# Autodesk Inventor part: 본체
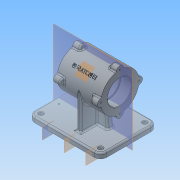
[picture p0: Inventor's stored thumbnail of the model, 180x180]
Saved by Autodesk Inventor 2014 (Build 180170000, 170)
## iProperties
Created: 2015-12
Part Number: 본체
Material: 일반
Document SubType Name: Modeling
Designer: nert
Density: 1 g/cm^3
Appearance: 기본값
Mass: 429.95 g
Surface Area: 814.906 cm^2
Volume: 429.95 cm^3
Author: nert
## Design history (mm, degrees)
sketch "스케치1"
  geometry: L1 (-70, 55)-(70, 55); L2 (70, 55)-(70, -55); L3 (70, -55)-(-70, -55); L4 (-70, -55)-(-70, 55); 3 further points
  constraints: 8 end point, 2 midpoint, 2 parallel, 1 horizontal, 1 horizontal alignment, 1 perpendicular, 1 vertical alignment
  dimensions: "d0" = 140 distance between parallel lines of L2 L4; "d1" = 110 distance between parallel lines of L3 L1
extrude "돌출1" new body sketch "스케치1" distance "d2" = 10; taper "d3" = 0 deg
node "작업 평면1"
node "작업 평면6"
  node "작업 평면5"
sketch "스케치5"
  geometry: C1 r 37 at (80, 55); 1 further point
  constraints: 1 centre point, 1 horizontal alignment
  dimensions: "d28" = 74 diameter of C1; "d29" = 80 distance of point (0, 55) C1.centre
extrude "돌출4" join sketch "스케치5" stored distance "d30" = 85; taper "d31" = 0 deg
sketch "스케치6"
  geometry: L1 (-52.5, 117)-(-52.5, 43) reference; L2 (-52.5, 80)-(32.5, 80); L3 (32.5, 43)-(32.5, 117) reference; L4 (-52.5, 103.5)-(-30.5, 103.5); L5 (-30.5, 103.5)-(-30.5, 80); L6 (-30.5, 101)-(10.5, 101); L7 (10.5, 101)-(10.5, 80); L8 (10.5, 101)-(10.5, 103.5); L9 (10.5, 103.5)-(32.5, 103.5); 1 further point
  constraints: 14 end point, 5 perpendicular, 5 point on line, 2 collinear, 2 midpoint, 1 horizontal
  dimensions: "d32" = 47 diameter of L4 L2; "d33" = 42 diameter of L6 L2; "d34" = 22 distance between parallel lines of L1 L5; "d35" = 22 distance between parallel lines of L3 L7
revolve "회전1" sketch "스케치6" stored, may be unused: angle "d36" = 90 deg
node "작업 평면7"
sketch "스케치7"
  geometry: L1 (-70, 55)-(70, 55) reference; L2 (70, 55)-(70, -55) reference; L3 (70, -55)-(-70, -55) reference; L4 (-70, -55)-(-70, 55) reference; L5 (14, 37)-(6, 37); L6 (6, 37)-(6, -37); L7 (6, -37)-(14, -37); L8 (14, -37)-(14, 37); 3 further points
  constraints: 8 end point, 3 midpoint, 2 parallel, 1 horizontal, 1 horizontal alignment, 1 perpendicular
  dimensions: "d38" = 8 distance between parallel lines of L6 L8; "d39" = 74 distance between parallel lines of L5 L7; "d40" = 80 distance from line of L4 point (10, 37); "d41" = 55 distance from line of point (6, 0) L3
extrude "돌출5" join sketch "스케치7" stored distance "d42" = 85; taper "d43" = 0 deg
node "작업 평면8"
node "작업 평면9"
node "작업 평면11"
node "작업 평면12"
sketch "스케치11"
  geometry: L1 (35, 6)-(-15, 6); L2 (-15, 6)-(-15, -6); L3 (-15, -6)-(35, -6); L4 (35, -6)-(35, 6); L5 (70, 55)-(70, -55) reference; 3 further points
  constraints: 8 end point, 2 midpoint, 2 parallel, 1 horizontal, 1 horizontal alignment, 1 perpendicular
  dimensions: "d58" = 35 distance between parallel lines of L5 L4; "d59" = 50 distance between parallel lines of L4 L2; "d60" = 12 distance between parallel lines of L1 L3
extrude "돌출7" join sketch "스케치11" stored distance "d61" = 12; taper "d62" = 0 deg
node "작업 평면13"
sketch "스케치12"
  geometry: L1 (-29, 0)-(-29, 33.49) reference; L2 (-8, 33.49)-(-29, 33.49) reference; L3 (21, 33.49)-(0, 33.49) reference; L4 (21, 0)-(21, 33.49) reference; L5 (-29, 0)-(-24.888, 33.49); L6 (-29, 0)-(-8, 0) reference; L7 (-8, 0)-(-8, 33.49) reference; L8 (21, 0)-(16.888, 33.49); L9 (0, 0)-(21, 0) reference; 1 further point
  constraints: 4 end point, 2 point on line
  dimensions: "d63" = 97 deg angle of L6 L5; "d64" = 97 deg angle of L9 L8
extrude "돌출8" cut sketch "스케치12" stored distance "d65" = 12; taper "d66" = 0 deg
node "작업 평면14"
sketch "스케치13"
  geometry: C1 r 23.5 at (0, 0) reference; C2 r 37 at (0, 0) reference; C3 r 23.5 at (0, 0); C4 r 37 at (0, 0); 1 further point
  constraints: 2 centre point, 2 coincident, 2 concentric
extrude "돌출9" join sketch "스케치13" stored distance "d67" = 50; taper "d68" = 0 deg
node "작업 평면15"
sketch "스케치14"
  geometry: A1 r 7 centre (-37, 0) between (-36.338, 6.969) and (-36.338, -6.969); A2 r 7 centre (0, -37) between (-6.969, -36.338) and (6.969, -36.338); A3 r 7 centre (37, 0) between (36.338, -6.969) and (36.338, 6.969); A4 r 7 centre (0, 37) between (6.969, 36.338) and (-6.969, 36.338); 2 further points
  constraints: 8 point on circle, 4 centre point, 3 equal radius, 2 horizontal alignment, 2 vertical alignment, 13 other
  dimensions: "d70" = 14 diameter of A1
extrude "돌출10" join sketch "스케치14" distance "d71" = 15; taper "d72" = 0 deg
node "작업 평면16"
node "작업 평면17"
node "작업 평면18"
sketch "스케치16"
  geometry: L1 (-52.5, 116.338)-(-52.5, 116.338) reference; L2 (-37.5, 116.338)-(-52.5, 116.338) reference; L3 (-37.5, 116.338)-(-37.5, 116.338) reference; L4 (-52.5, 116.338)-(-37.5, 116.338) reference; L5 (-52.5, 124)-(-37.5, 124) reference; L6 (-37.5, 117)-(17.5, 117) reference; L7 (-40.289, 124)-(-37.5, 124); L8 (-37.5, 116.338)-(-40.289, 124); L9 (-40.289, 124)-(-40.289, 124); L10 (-37.5, 116.338)-(-37.5, 124); 1 further point
  constraints: 8 end point, 2 point on line, 1 perpendicular
  dimensions: "d85" = 110 deg angle of L2 L8
extrude "돌출11" cut sketch "스케치16" stored distance "d86" = 15; taper "d87" = 0 deg
node "작업 평면19"
node "작업 평면20"
sketch "스케치17"
  geometry: L1 (-70, -55)-(70, -55) reference; L2 (-70, 55)-(-70, -55) reference; C1 r 4 at (-58, -43); 1 further point
  constraints: 1 centre point
  dimensions: "d92" = 12 distance from line of L1 C1.centre; "d93" = 12 distance from line of C1.centre L2; "d94" = 8 diameter of C1
extrude "돌출12" cut sketch "스케치17" distance "d95" = 15; taper "d96" = 0 deg
node "작업 평면21"
node "작업 평면22"
fillet "모깎기2" dims "d98" = 3
node "작업 평면23"
sketch "스케치18"
  geometry: C1 r 37 at (80, 55); C2 r 21 at (80, 55) reference; C3 r 23.5 at (80, 55) reference; C4 r 23.5 at (80, 55); A1 r 37 centre (80, 55) between (86.969, 18.662) and (116.338, 48.031) reference; 1 further point
  constraints: 2 centre point, 2 coincident, 1 concentric
  dimensions: "d99" = 74 diameter of C1
extrude "돌출13" join sketch "스케치18" stored distance "d100" = 85; taper "d101" = 0 deg
fillet "모깎기3" dims "d102" = 3
node "작업 평면29"
sketch "스케치19"
  geometry: A1 r 7 centre (117, 55) between (118.239, 48.111) and (118.239, 61.889) reference; 2 further points
  constraints: 1 coincident
hole "구멍2" sketch "스케치19" at (117, 55) diameter "d104" = 3.242; stored, may be unused: countersink angle "d108" = 90 deg, drill point angle "d110" = 118 deg; dims "d105" = 9, "d106" = 4, "d107" = 2, "d109" = 11
node "작업 평면31"
sketch "스케치20"
  geometry: C1 r 23.5 at (-80, 55) reference; A1 r 7 centre (-43, 55) between (-41.761, 48.111) and (-41.761, 61.889) reference; A2 r 3 centre (-41.23, 64.842) between (-44.138, 64.104) and (-41.761, 61.889) reference; A3 r 37 centre (-80, 55) between (-44.138, 64.104) and (-70.896, 90.862) reference; A4 r 3 centre (-70.158, 93.77) between (-73.111, 93.239) and (-70.896, 90.862) reference; A5 r 7 centre (-80, 92) between (-73.111, 93.239) and (-86.889, 93.239) reference; A6 r 3 centre (-89.842, 93.77) between (-89.104, 90.862) and (-86.889, 93.239) reference; A7 r 37 centre (-80, 55) between (-89.104, 90.862) and (-115.862, 64.104) reference; A8 r 3 centre (-118.77, 64.842) between (-118.239, 61.889) and (-115.862, 64.104) reference; A9 r 7 centre (-117, 55) between (-118.239, 61.889) and (-118.239, 48.111) reference; A10 r 3 centre (-118.77, 45.158) between (-115.862, 45.896) and (-118.239, 48.111) reference; A11 r 37 centre (-80, 55) between (-115.862, 45.896) and (-89.104, 19.137) reference; A12 r 3 centre (-89.842, 16.23) between (-86.889, 16.761) and (-89.104, 19.137) reference; A13 r 7 centre (-80, 18) between (-86.889, 16.761) and (-73.111, 16.761) reference; A14 r 3 centre (-70.158, 16.23) between (-70.896, 19.137) and (-73.111, 16.761) reference; A15 r 37 centre (-80, 55) between (-70.896, 19.137) and (-44.138, 45.896) reference; A16 r 3 centre (-41.23, 45.158) between (-41.761, 48.111) and (-44.138, 45.896) reference; 4 further points
  constraints: 3 coincident
hole "구멍3" sketch "스케치20" at (-80, 92), (-43, 55), (-80, 18) diameter "d115" = 3.242; stored, may be unused: countersink angle "d119" = 90 deg, drill point angle "d121" = 118 deg; dims "d116" = 9, "d117" = 4, "d118" = 2, "d120" = 11
fillet "모깎기4" dims "d122" = 12
fillet "모깎기5" dims "d123" = 3
chamfer "모따기1" distance "d124" = 1; stored, may be unused: second distance "d125" = 2, angle "d126" = 45 deg
chamfer "모따기2" distance "d127" = 1; stored, may be unused: second distance "d128" = 2, angle "d129" = 45 deg
chamfer "모따기3" distance "d130" = 0.3; stored, may be unused: second distance "d131" = 2, angle "d132" = 45 deg
node "작업 평면32"
sketch "스케치21"
  geometry: L1 (-80, 55)-(-106.163, 28.837); L2 (-80, 11)-(-80, 99); C1 r 24.5 at (-80, 55) reference; A1 r 37 centre (-80, 55) between (-70.896, 19.137) and (-44.138, 45.896) reference; A2 r 3 centre (-70.158, 16.23) between (-70.896, 19.137) and (-73.111, 16.761) reference; A3 r 7 centre (-80, 18) between (-86.889, 16.761) and (-73.111, 16.761) reference; A4 r 3 centre (-89.842, 16.23) between (-86.889, 16.761) and (-89.104, 19.137) reference; A5 r 37 centre (-80, 55) between (-115.862, 45.896) and (-89.104, 19.137) reference; A6 r 3 centre (-118.77, 45.158) between (-115.862, 45.896) and (-118.239, 48.111) reference; A7 r 7 centre (-117, 55) between (-118.239, 61.889) and (-118.239, 48.111) reference; A8 r 3 centre (-118.77, 64.842) between (-118.239, 61.889) and (-115.862, 64.104) reference; A9 r 37 centre (-80, 55) between (-89.104, 90.862) and (-115.862, 64.104) reference; A10 r 3 centre (-89.842, 93.77) between (-89.104, 90.862) and (-86.889, 93.239) reference; A11 r 7 centre (-80, 92) between (-73.111, 93.239) and (-86.889, 93.239) reference; A12 r 3 centre (-70.158, 93.77) between (-73.111, 93.239) and (-70.896, 90.862) reference; A13 r 37 centre (-80, 55) between (-44.138, 64.104) and (-70.896, 90.862) reference; A14 r 3 centre (-41.23, 64.842) between (-44.138, 64.104) and (-41.761, 61.889) reference; A15 r 7 centre (-43, 55) between (-41.761, 48.111) and (-41.761, 61.889) reference; A16 r 3 centre (-41.23, 45.158) between (-41.761, 48.111) and (-44.138, 45.896) reference; 1 further point
  constraints: 4 end point, 3 point on circle
  dimensions: "d133" = 45 deg angle of L2 L1
  node "투영된 루프9"
node "작업 평면30"
fillet "모깎기6" dims "d137" = 3
node "작업 평면33"
sketch "스케치23"
  geometry: A1 r 7 centre (-117, 55) between (-118.239, 61.889) and (-118.239, 48.111) reference; 2 further points
  constraints: 1 coincident
hole "구멍4" sketch "스케치23" at (-117, 55) diameter "d139" = 3.242; stored, may be unused: countersink angle "d143" = 90 deg, drill point angle "d145" = 118 deg; dims "d140" = 9, "d141" = 4, "d142" = 2, "d144" = 11
sketch "스케치24"
  geometry: 1 further point
node "작업 평면34"
sketch "스케치25"
  geometry: L1 (-42.5, 18.921)-(-42.5, -18.921) reference; L2 (42.5, -18.921)-(42.5, 18.921) reference; 3 further points
  constraints: 1 horizontal alignment, 1 midpoint, 1 other
  dimensions: "d147" = 42.5 distance from line of point (0, 0) L1
feature "엠보싱2" sketch "스케치25" dims "d148" = 0.5, "d149" = 0
node "솔리드1"
mirror "대칭2"
pattern_circular "원형 패턴1" dims angle "d89" = 360 deg
mirror "대칭4"
mirror "대칭5"
mirror "대칭6"
pattern_circular "원형 패턴2" dims angle "d112" = 360 deg
node "투영된 루프3"
node "투영된 루프6"
node "투영된 루프7"
node "투영된 루프8"
other parameters: "d4" = 0, "d7" = 8, "d8" = 12, "d26" = 0, "d37" = 0, "d44" = 0, "d57" = 0, "d69" = 0, "d73" = 0, "d91" = 0, "d138" = 0, "d146" = 0.5
